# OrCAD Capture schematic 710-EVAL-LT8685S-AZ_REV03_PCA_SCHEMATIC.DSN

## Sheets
1 LT8685S: size Custom; note: 42V,QUAD GANGABLE,
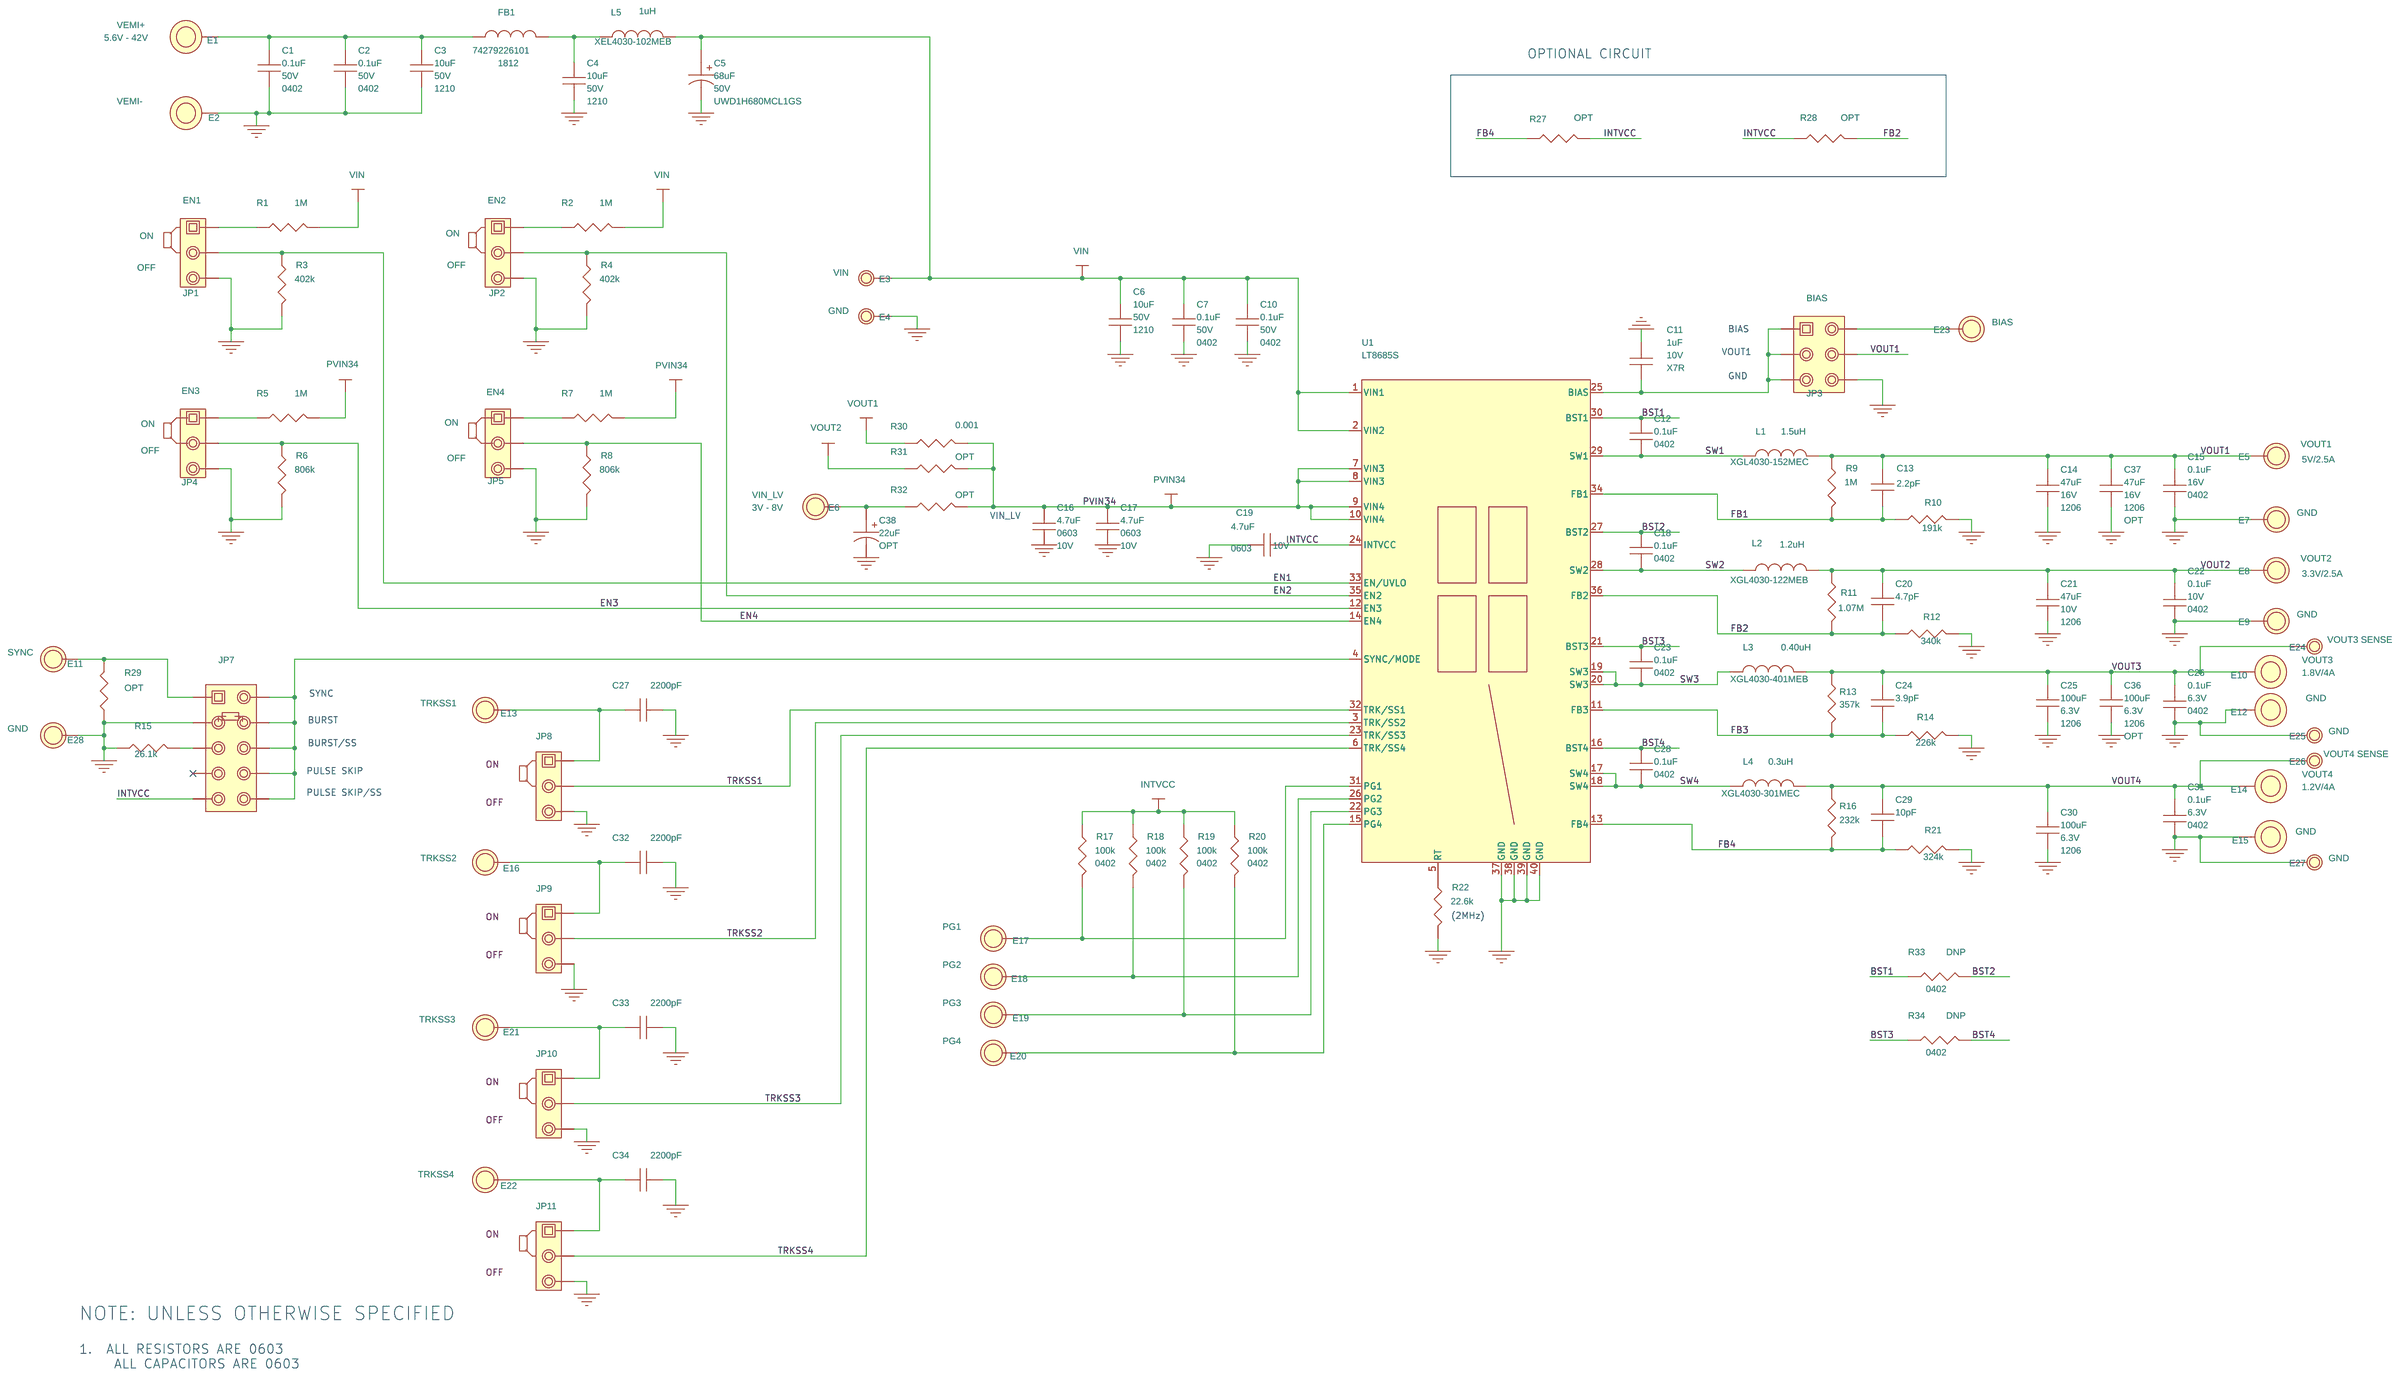
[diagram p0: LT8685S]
2 PAGE2
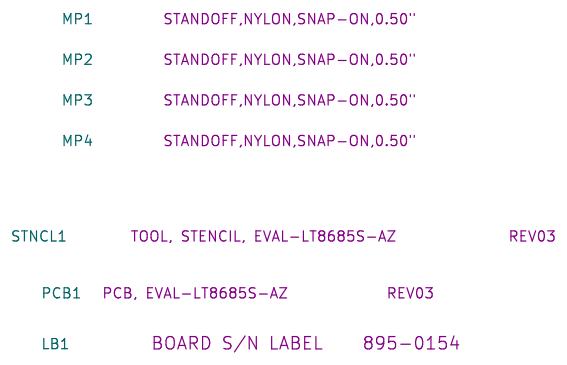
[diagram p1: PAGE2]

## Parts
sheet LT8685S
C1  0.1uF  [CC0402N]
C2  0.1uF  [CC0402N]
C3  10uF  [CC1210N]
C4  10uF  [CC1210N]
C5  68uF  [NICHICON_UWD_8x10]
C6  10uF  [CC1210N]
C7  0.1uF  [CC0402N]
C10  0.1uF  [CC0402N]
C11  1uF  [CC0603N]
C12  0.1uF  [CC0402N]
C13  2.2pF  [CC0603N]
C14  47uF  [CC1206N]
C15  0.1uF  [CC0402N]
C16  4.7uF  [CC0603N]
C17  4.7uF  [CC0603N]
C18  0.1uF  [CC0402N]
C19  4.7uF  [CC0603N]
C20  4.7pF  [CC0603N]
C21  47uF  [CC1206N]
C22  0.1uF  [CC0402N]
C23  0.1uF  [CC0402N]
C24  3.9pF  [CC0603N]
C25  100uF  [CC1206N]
C26  0.1uF  [CC0402N]
C27  2200pF  [CC0603N]
C28  0.1uF  [CC0402N]
C29  10pF  [CC0603N]
C30  100uF  [CC1206N]
C31  0.1uF  [CC0402N]
C32  2200pF  [CC0603N]
C33  2200pF  [CC0603N]
C34  2200pF  [CC0603N]
C36  100uF  [CC1206N]
C37  47uF  [CC1206N]
C38  22uF  [SUNCON_CE-BSS_6.3X5.4]
E1  BANANA JACK  [KEY-575-4]
E2  BANANA JACK  [KEY-575-4]
E3  TEST POINT  [MILLMAX2308]
E4  TEST POINT  [MILLMAX2308]
E5  TEST POINT  [MILLMAX2501]
E6  TEST POINT  [MILLMAX2501]
E7  TEST POINT  [MILLMAX2501]
E8  TEST POINT  [MILLMAX2501]
E9  TEST POINT  [MILLMAX2501]
E10  BANANA JACK  [KEY-575-4]
E11  TEST POINT  [MILLMAX2501]
E12  BANANA JACK  [KEY-575-4]
E13  TEST POINT  [MILLMAX2501]
E14  BANANA JACK  [KEY-575-4]
E15  BANANA JACK  [KEY-575-4]
E16  TEST POINT  [MILLMAX2501]
E17  TEST POINT  [MILLMAX2501]
E18  TEST POINT  [MILLMAX2501]
E19  TEST POINT  [MILLMAX2501]
E20  TEST POINT  [MILLMAX2501]
E21  TEST POINT  [MILLMAX2501]
E22  TEST POINT  [MILLMAX2501]
E23  TEST POINT  [MILLMAX2501]
E24  TEST POINT  [MILLMAX2308]
E25  TEST POINT  [MILLMAX2308]
E26  TEST POINT  [MILLMAX2308]
E27  TEST POINT  [MILLMAX2308]
E28  TEST POINT  [MILLMAX2501]
FB1  100 OHMS@100MHz  [WURTH-1812]
JP1  HDR  [HD1X3-079]
JP2  HDR  [HD1X3-079]
JP3  HDR  [HD2X3-079]
JP4  HDR  [HD1X3-079]
JP5  HDR  [HD1X3-079]
JP7  HDR  [HD2X5-079]
JP8  HDR  [HD1X3-079]
JP9  HDR  [HD1X3-079]
JP10  HDR  [HD1X3-079]
JP11  HDR  [HD1X3-079]
L1  1.5uH  [COILCRAFT-XGL4030]
L2  1.2uH  [COILCRAFT-XGL4030]
L3  0.40uH  [COILCRAFT-XGL4030]
L4  0.3uH  [COILCRAFT-XGL4030]
L5  1uH  [COILCRAFT-XEL4030]
R1  1M  [CR0603N]
R2  1M  [CR0603N]
R3  402k  [CR0603N]
R4  402k  [CR0603N]
R5  1M  [CR0603N]
R6  806k  [CR0603N]
R7  1M  [CR0603N]
R8  806k  [CR0603N]
R9  1M  [CR0603N]
R10  191k  [CR0603N]
R11  1.07M  [CR0603N]
R12  340k  [CR0603N]
R13  357k  [CR0603N]
R14  226k  [CR0603N]
R15  26.1k  [CR0603N]
R16  232k  [CR0603N]
R17  100k  [CR0402N]
R18  100k  [CR0402N]
R19  100k  [CR0402N]
R20  100k  [CR0402N]
R21  324k  [CR0603N]
R22  22.6k  [CR0603N]
R27  OPT  [CR0603N]
R28  OPT  [CR0603N]
R29  OPT  [CR0603N]
R30  0.001  [SUSUMU-KRL2012]
R31  0.001  [SUSUMU-KRL2012]
R32  0.001  [SUSUMU-KRL2012]
R33  OPT  [CR0402N]
R34  OPT  [CR0402N]
U1  LT8685S  [LTC-LQFN-36-7056]
XJP1  SHUNT
XJP2  SHUNT
XJP3  SHUNT
XJP4  SHUNT
XJP5  SHUNT
XJP7  SHUNT
XJP8  SHUNT
XJP9  SHUNT
XJP10  SHUNT
XJP11  SHUNT
sheet PAGE2
LB1  LABEL  [895-0154_REV01]
MP1  STANDOFF  [KEYSTONE_8829-8834]
MP2  STANDOFF  [KEYSTONE_8829-8834]
MP3  STANDOFF  [KEYSTONE_8829-8834]
MP4  STANDOFF  [KEYSTONE_8829-8834]
PCB1  PCB, EVAL-LT8685S-AZ
STNCL1  TOOL, STENCIL, EVAL-LT8685S-AZ

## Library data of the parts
C1 C2 C7 C10 = CAP: CAP.,0.1uF,X7R,50V,10%,0402; CLASS: DISCRETE; Dielectric Type: X7R; FPLIST: CC0402N,CC0402L,CC0402M; Inventory Qty: 321916; Manufacturer: AVX; Manufacturer PN: 04025C104KAT2A; PART_NUMBER: 150-3240; Package Size: 0402; Package Type: SMD; Rated Voltage: 50V; Tolerance: 10%
C3 C4 C6 = CAP: CAP.,10uF,X7R,50V,10%,1210,NO SUBS. ALLOWED; CLASS: DISCRETE; Dielectric Type: X7R; FPLIST: CC1210N,CC1210L,CC1210M; Inventory Qty: 191942; Manufacturer: MURATA; Manufacturer PN: GRM32ER71H106KA12L; PART_NUMBER: 150-3043; Package Size: 1210; Package Type: SMD; Rated Voltage: 50V; Tolerance: 10%
C5 = CAP_P_ALT: CAP.,68uF,ALUM ELECT.,50V,20%,SMD,8x10mm,AEC-Q200; CLASS: DISCRETE; Dielectric Type: ALUM ELECT.; Inventory Qty: 0; Manufacturer: Nichicon; Manufacturer PN: UWD1H680MCL1GS; PART_NUMBER: 150-1006; Package Size: SMD,8x10mm; Package Type: Surface Mount; Rated Voltage: 50V; Tolerance: 20%
C11 = CAP: CAP.,1uF,X7R,10V,10%,0603; CLASS: DISCRETE; Dielectric Type: X7R; FPLIST: CC0603N,CC0603L,CC0603M; Inventory Qty: 56548; Manufacturer: AVX; Manufacturer PN: 0603ZC105KAT2A; Material: X7R; PART_NUMBER: 150-3414; Package Size: 0603; Rated Voltage: 10V; Tolerance: 10%; Voltage Level: 10V
C12 C18 C23 C28 = CAP: CAP.,0.1uF,X7R,16V,10%,0402; CLASS: DISCRETE; Dielectric Type: X7R; FPLIST: CC0402N,CC0402L,CC0402M; Inventory Qty: 324549; Manufacturer: AVX; Manufacturer PN: 0402YC104KAT2A; PART_NUMBER: 150-2081; Package Size: 0402; Rated Voltage: 16V; Tolerance: 10%
C13 = CAP: CAP.,2.2pF,C0G/NP0,50V,+/-0.25pF,0603; CLASS: DISCRETE; Dielectric Type: C0G/NP0; FPLIST: CC0603N,CC0603L,CC0603M; Inventory Qty: 13646; Manufacturer: AVX; Manufacturer PN: 06035A2R2CAT2A; PART_NUMBER: 150-0030; Package Size: 0603; Rated Voltage: 50V; Tolerance: +/-0.25pF
C14 = CAP: CAP.,47uF,X5R,16V,20%,1206; CLASS: DISCRETE; Dielectric Type: X5R; FPLIST: CC1206N,CC1206L,CC1206M; Inventory Qty: 4594; Manufacturer: AVX; Manufacturer PN: 1206YD476MAT2A; Material: X7R; PART_NUMBER: 150-3243; Package Size: 1206; Package Type: SMD; Rated Voltage: 16V; Tolerance: 20%; Voltage Level: 16V
C15 = CAP: CAP.,0.1uF,X7R,16V,10%,0402; CLASS: DISCRETE; Dielectric Type: X7R; FPLIST: CC0402N,CC0402L,CC0402M; Inventory Qty: 324549; Manufacturer: AVX; Manufacturer PN: 0402YC104KAT2A; Material: X7R; PART_NUMBER: 150-2081; Package Size: 0402; Rated Voltage: 16V; Tolerance: 10%; Voltage Level: 16V
C16 C17 C19 = CAP: CAP.,4.7uF,X5R,10V,10%,0603; CLASS: DISCRETE; Dielectric Type: X5R; FPLIST: CC0603N,CC0603L,CC0603M; Inventory Qty: 20774; Manufacturer: AVX; Manufacturer PN: 0603ZD475KAT2A; Material: X7R; PART_NUMBER: 150-3050; Package Size: 0603; Rated Voltage: 10V; Tolerance: 10%; Voltage Level: 10V
C20 = CAP: CAP.,4.7pF,C0G/NP0,50V,+/-0.25pF,0603; CLASS: DISCRETE; Dielectric Type: C0G/NP0; FPLIST: CC0603N,CC0603L,CC0603M; Inventory Qty: 22709; Manufacturer: MURATA; Manufacturer PN: GRM1885C1H4R7CA01D; PART_NUMBER: 150-2223; Package Size: 0603; Rated Voltage: 50V; Tolerance: +/-0.25pF
C21 = CAP: CAP.,47uF,X5R,10V,10%,1206; CLASS: DISCRETE; Dielectric Type: X5R; FPLIST: CC1206N,CC1206L,CC1206M; Inventory Qty: 3750; Manufacturer: MURATA; Manufacturer PN: GRM31CR61A476KE15L; Material: X7R; PART_NUMBER: 150-3310; Package Size: 1206; Rated Voltage: 10V; Tolerance: 10%; Voltage Level: 10V
C22 = CAP: CAP.,0.1uF,X7R,10V,10%,0402; CLASS: DISCRETE; Dielectric Type: X7R; FPLIST: CC0402N,CC0402L,CC0402M; Inventory Qty: 92320; Manufacturer: MURATA; Manufacturer PN: GRM155R71A104KA01D; Material: X7R; PART_NUMBER: 150-0331; Package Size: 0402; Rated Voltage: 10V; Tolerance: 10%; Voltage Level: 10V
C24 = CAP: CAP.,3.9pF,C0G,50V,5%,0603; CLASS: DISCRETE; Dielectric Type: C0G; FPLIST: CC0603N,CC0603L,CC0603M; Inventory Qty: 202; Manufacturer: AVX; Manufacturer PN: 06035A3R9JAT2A; PART_NUMBER: 150-0276; Package Size: 0603; Rated Voltage: 50V; Tolerance: 5%
C25 C30 = CAP: CAP.,100uF,X5R,6.3V,10%,1206; CLASS: DISCRETE; Dielectric Type: X5R; FPLIST: CC1206N,CC1206L,CC1206M; Inventory Qty: 5866; Manufacturer: MURATA; Manufacturer PN: GRM31CR60J107KE39L; PART_NUMBER: 150-2327; Package Size: 1206; Rated Voltage: 6.3V; Tolerance: 10%
C26 C31 = CAP: CAP.,0.1uF,X5R,6.3V,20%,0402; CLASS: DISCRETE; Dielectric Type: X5R; FPLIST: CC0402N,CC0402L,CC0402M; Inventory Qty: 716; Manufacturer: AVX; Manufacturer PN: 04026D104MAT2A; Material: X7R; PART_NUMBER: 150-0498; Package Size: 0402; Rated Voltage: 6.3V; Tolerance: 20%; Voltage Level: 6.3V
C27 C32-C34 = CAP: CAP.,2200pF,X7R,25V,10%,0603; CLASS: DISCRETE; Dielectric Type: X7R; FPLIST: CC0603N,CC0603L,CC0603M; Inventory Qty: 24218; Manufacturer: AVX; Manufacturer PN: 06033C222KAT2A; PART_NUMBER: 150-2372; Package Size: 0603; Rated Voltage: 25V; Tolerance: 10%
C29 = CAP: CAP.,10pF,C0G,50V,5%,0603; CLASS: DISCRETE; Dielectric Type: C0G; FPLIST: CC0603N,CC0603L,CC0603M; Inventory Qty: 6220; Manufacturer: AVX; Manufacturer PN: 06035A100JAT2A; PART_NUMBER: 150-0023; Package Size: 0603; Rated Voltage: 50V; Tolerance: 5%
C36 = CAP: CAP.,100uF,X5R,6.3V,10%,1206; CLASS: DISCRETE; Dielectric Type: X5R; FPLIST: CC1206N,CC1206L,CC1206M; Inventory Qty: 5866; Manufacturer: MURATA; Manufacturer PN: GRM31CR60J107KE39L; PART_FIELD_01: OPT; PART_NUMBER: 150-2327; Package Size: 1206; Rated Voltage: 6.3V; Tolerance: 10%
C37 = CAP: CAP.,47uF,X5R,16V,20%,1206; CLASS: DISCRETE; Dielectric Type: X5R; FPLIST: CC1206N,CC1206L,CC1206M; Inventory Qty: 4594; Manufacturer: AVX; Manufacturer PN: 1206YD476MAT2A; Material: X7R; PART_FIELD_01: OPT; PART_NUMBER: 150-3243; Package Size: 1206; Package Type: SMD; Rated Voltage: 16V; Tolerance: 20%; Voltage Level: 16V
C38 = CAP_P_ALT: CAP.,22uF,ALUM ELECT,50V,20%,6.3x5.4mm,RADIAL,SMD,CE-BSS Series,AEC-Q200; 9th Part Field: OPT; CLASS: DISCRETE; Dielectric Type: ALUM ELECT; FPLIST: SUNCON_CE-BSS_6.3X5.4,SUNCON_CE-BSS_6-3X5-4; Inventory Qty: 290; Manufacturer: SUN ELECTRONIC INDUSTRIES CORP; Manufacturer PN: 50CE22BSS; PART_NUMBER: 150-3499; Package Size: 6.3x5.4mm,RADIAL,SMD; Rated Voltage: 50V; Tolerance: 20%
E1 = BANANA_KEYSTONE-575-4: CONN.,BANANA JACK,FEMALE,THT,NON-INSULATED,SWAGE,0.218"; CLASS: IO; Inventory Qty: 203061; Manufacturer: KEYSTONE; Manufacturer PN: 575-4; PART_FIELD_01: VEMI+; PART_FIELD_02: 5.6V - 42V; PART_NUMBER: 250-0428
E2 = BANANA_KEYSTONE-575-4: CONN.,BANANA JACK,FEMALE,THT,NON-INSULATED,SWAGE,0.218"; CLASS: IO; Inventory Qty: 203061; Manufacturer: KEYSTONE; Manufacturer PN: 575-4; PART_FIELD_01: VEMI-; PART_FIELD_02: 3V - 42V; PART_NUMBER: 250-0428
E3 = TEST_POINT_.156_MILL-MAX_2308_A: TEST POINT,TURRET,0.064" MTG. HOLE,PCB 0.062" THK; CLASS: IO; Inventory Qty: 1142083; Manufacturer: MILL-MAX; Manufacturer PN: 2308-2-00-80-00-00-07-0; PART_FIELD_1: VIN; PART_NUMBER: 260-0004
E4 E25 E27 = TEST_POINT_.156_MILL-MAX_2308_A: TEST POINT,TURRET,0.064" MTG. HOLE,PCB 0.062" THK; CLASS: IO; Inventory Qty: 1142083; Manufacturer: MILL-MAX; Manufacturer PN: 2308-2-00-80-00-00-07-0; PART_FIELD_1: GND; PART_NUMBER: 260-0004
E5 = TURRET_A: TEST POINT,TURRET,0.094" MTG. HOLE,PCB 0.062" THK; CLASS: IO; Inventory Qty: 823526; Manufacturer: MILL-MAX; Manufacturer PN: 2501-2-00-80-00-00-07-0; PART_FIELD_01: VOUT1; PART_FIELD_02: 5V/2.5A; PART_NUMBER: 260-0003
E6 = TURRET_A: TEST POINT,TURRET,0.094" MTG. HOLE,PCB 0.062" THK; CLASS: IO; Inventory Qty: 823526; Manufacturer: MILL-MAX; Manufacturer PN: 2501-2-00-80-00-00-07-0; PART_FIELD_01: VIN_LV; PART_FIELD_02: 3V - 8V; PART_NUMBER: 260-0003
E7 E9 E28 = TURRET_A: TEST POINT,TURRET,0.094" MTG. HOLE,PCB 0.062" THK; CLASS: IO; Inventory Qty: 823526; Manufacturer: MILL-MAX; Manufacturer PN: 2501-2-00-80-00-00-07-0; PART_FIELD_01: GND; PART_NUMBER: 260-0003
E8 = TURRET_A: TEST POINT,TURRET,0.094" MTG. HOLE,PCB 0.062" THK; CLASS: IO; Inventory Qty: 823526; Manufacturer: MILL-MAX; Manufacturer PN: 2501-2-00-80-00-00-07-0; PART_FIELD_01: VOUT2; PART_FIELD_02: 3.3V/2.5A; PART_NUMBER: 260-0003
E10 = BANANA_KEYSTONE-575-4: CONN.,BANANA JACK,FEMALE,THT,NON-INSULATED,SWAGE,0.218"; CLASS: IO; Inventory Qty: 203061; Manufacturer: KEYSTONE; Manufacturer PN: 575-4; PART_FIELD_01: VOUT3; PART_FIELD_02: 1.8V/4A; PART_NUMBER: 250-0428
E11 = TURRET_A: TEST POINT,TURRET,0.094" MTG. HOLE,PCB 0.062" THK; CLASS: IO; Inventory Qty: 823526; Manufacturer: MILL-MAX; Manufacturer PN: 2501-2-00-80-00-00-07-0; PART_FIELD_01: SYNC; PART_NUMBER: 260-0003
E12 E15 = BANANA_KEYSTONE-575-4: CONN.,BANANA JACK,FEMALE,THT,NON-INSULATED,SWAGE,0.218"; CLASS: IO; Inventory Qty: 203061; Manufacturer: KEYSTONE; Manufacturer PN: 575-4; PART_FIELD_01: GND; PART_FIELD_02: 5V/2A; PART_NUMBER: 250-0428
E13 = TURRET_A: TEST POINT,TURRET,0.094" MTG. HOLE,PCB 0.062" THK; CLASS: IO; Inventory Qty: 823526; Manufacturer: MILL-MAX; Manufacturer PN: 2501-2-00-80-00-00-07-0; PART_FIELD_01: TRKSS1; PART_NUMBER: 260-0003
E14 = BANANA_KEYSTONE-575-4: CONN.,BANANA JACK,FEMALE,THT,NON-INSULATED,SWAGE,0.218"; CLASS: IO; Inventory Qty: 203061; Manufacturer: KEYSTONE; Manufacturer PN: 575-4; PART_FIELD_01: VOUT4; PART_FIELD_02: 1.2V/4A; PART_NUMBER: 250-0428
E16 = TURRET_A: TEST POINT,TURRET,0.094" MTG. HOLE,PCB 0.062" THK; CLASS: IO; Inventory Qty: 823526; Manufacturer: MILL-MAX; Manufacturer PN: 2501-2-00-80-00-00-07-0; PART_FIELD_01: TRKSS2; PART_NUMBER: 260-0003
E17 = TURRET_A: TEST POINT,TURRET,0.094" MTG. HOLE,PCB 0.062" THK; CLASS: IO; Inventory Qty: 823526; Manufacturer: MILL-MAX; Manufacturer PN: 2501-2-00-80-00-00-07-0; PART_FIELD_01: PG1; PART_NUMBER: 260-0003
E18 = TURRET_A: TEST POINT,TURRET,0.094" MTG. HOLE,PCB 0.062" THK; CLASS: IO; Inventory Qty: 823526; Manufacturer: MILL-MAX; Manufacturer PN: 2501-2-00-80-00-00-07-0; PART_FIELD_01: PG2; PART_NUMBER: 260-0003
E19 = TURRET_A: TEST POINT,TURRET,0.094" MTG. HOLE,PCB 0.062" THK; CLASS: IO; Inventory Qty: 823526; Manufacturer: MILL-MAX; Manufacturer PN: 2501-2-00-80-00-00-07-0; PART_FIELD_01: PG3; PART_NUMBER: 260-0003
E20 = TURRET_A: TEST POINT,TURRET,0.094" MTG. HOLE,PCB 0.062" THK; CLASS: IO; Inventory Qty: 823526; Manufacturer: MILL-MAX; Manufacturer PN: 2501-2-00-80-00-00-07-0; PART_FIELD_01: PG4; PART_NUMBER: 260-0003
E21 = TURRET_A: TEST POINT,TURRET,0.094" MTG. HOLE,PCB 0.062" THK; CLASS: IO; Inventory Qty: 823526; Manufacturer: MILL-MAX; Manufacturer PN: 2501-2-00-80-00-00-07-0; PART_FIELD_01: TRKSS3; PART_NUMBER: 260-0003
E22 = TURRET_A: TEST POINT,TURRET,0.094" MTG. HOLE,PCB 0.062" THK; CLASS: IO; Inventory Qty: 823526; Manufacturer: MILL-MAX; Manufacturer PN: 2501-2-00-80-00-00-07-0; PART_FIELD_01: TRKSS4; PART_NUMBER: 260-0003
E23 = TURRET_A: TEST POINT,TURRET,0.094" MTG. HOLE,PCB 0.062" THK; CLASS: IO; Inventory Qty: 823526; Manufacturer: MILL-MAX; Manufacturer PN: 2501-2-00-80-00-00-07-0; PART_FIELD_01: BIAS; PART_NUMBER: 260-0003
E24 = TEST_POINT_.156_MILL-MAX_2308_A: TEST POINT,TURRET,0.064" MTG. HOLE,PCB 0.062" THK; CLASS: IO; Inventory Qty: 1142083; Manufacturer: MILL-MAX; Manufacturer PN: 2308-2-00-80-00-00-07-0; PART_FIELD_1: VOUT3 SENSE; PART_NUMBER: 260-0004
E26 = TEST_POINT_.156_MILL-MAX_2308_A: TEST POINT,TURRET,0.064" MTG. HOLE,PCB 0.062" THK; CLASS: IO; Inventory Qty: 1142083; Manufacturer: MILL-MAX; Manufacturer PN: 2308-2-00-80-00-00-07-0; PART_FIELD_1: VOUT4 SENSE; PART_NUMBER: 260-0004
FB1 = IND: IND.,100 OHMS@100MHz,FERRITE BEAD,25%,8A,6mOHMS,1812; CLASS: DISCRETE; FPLIST: WURTH-1812,WURTH-74279226101; Inventory Qty: 3043; Manufacturer: WURTH ELEKTRONIK; Manufacturer PN: 74279226101; PART_NUMBER: 200-0280; Package Size: 1812; Tolerance: 25%
JP1 = 1X3_A: CONN.,HDR,MALE,1x3,2mm,VERT,ST,THT,NO SUBS. ALLOWED; 10th Part Field: ON; 11th Part Field: OFF; 12th Part Field: 12th; 9th Part Field: EN1; CLASS: IO; Inventory Qty: 28997; Manufacturer: Wurth Elektronik; Manufacturer PN: 62000311121; PART_NUMBER: 250-0639
JP2 = 1X3_A: CONN.,HDR,MALE,1x3,2mm,VERT,ST,THT,NO SUBS. ALLOWED; 10th Part Field: ON; 11th Part Field: OFF; 12th Part Field: 12th; 9th Part Field: EN2; CLASS: IO; Inventory Qty: 28997; Manufacturer: Wurth Elektronik; Manufacturer PN: 62000311121; PART_NUMBER: 250-0639
JP3 = HDR2X3_ALT1: CONN.,HDR,MALE,2x3,2mm,VERT,ST,THT; 9th Part Field: BIAS; CLASS: IO; Inventory Qty: 17651; Manufacturer: WURTH ELEKTRONIK; Manufacturer PN: 62000621121; PART_NUMBER: 250-0483
JP4 = 1X3_A: CONN.,HDR,MALE,1x3,2mm,VERT,ST,THT,NO SUBS. ALLOWED; 10th Part Field: ON; 11th Part Field: OFF; 12th Part Field: 12th; 9th Part Field: EN3; CLASS: IO; Inventory Qty: 28997; Manufacturer: Wurth Elektronik; Manufacturer PN: 62000311121; PART_NUMBER: 250-0639
JP5 = 1X3_A: CONN.,HDR,MALE,1x3,2mm,VERT,ST,THT,NO SUBS. ALLOWED; 10th Part Field: ON; 11th Part Field: OFF; 12th Part Field: 12th; 9th Part Field: EN4; CLASS: IO; Inventory Qty: 28997; Manufacturer: Wurth Elektronik; Manufacturer PN: 62000311121; PART_NUMBER: 250-0639
JP7 = HDR2X5_ALT1: CONN.,HDR,MALE,2x5,2mm,VERT,ST,THT; CLASS: IO; Inventory Qty: 246; Manufacturer: WURTH ELEKTRONIK; Manufacturer PN: 62001021121; PART_NUMBER: 250-0679
JP8-JP11 = 1X3_A: CONN.,HDR,MALE,1x3,2mm,VERT,ST,THT,NO SUBS. ALLOWED; 10th Part Field: 10th; 11th Part Field: 11th; 12th Part Field: 12th; 9th Part Field: 9th; CLASS: IO; Inventory Qty: 28997; Manufacturer: Wurth Elektronik; Manufacturer PN: 62000311121; PART_NUMBER: 250-0639
L1 = IND: IND.,1.5uH,PWR,20%,10.2A,10.5mOHMS,SMD,AEC-Q200; CLASS: DISCRETE; Inventory Qty: 0; Manufacturer: COILCRAFT; Manufacturer PN: XGL4030-152MEC; PART_NUMBER: 200-0423; Package Size: SMD; Tolerance: 20%
L2 = IND: IND.,1.2uH,PWR,20%,12.2A,9.4mOHMS,SMD,AEC-Q200,SHIELDED; CLASS: DISCRETE; Inventory Qty: 0; Manufacturer: COILCRAFT; Manufacturer PN: XGL4030-122MEB; PART_NUMBER: 200-0407; Package Size: SMD; Tolerance: 20%
L3 = IND: IND.,0.40uH,PWR,20%,22.5A,32.8mOHMS,SMD,AEC-Q200; CLASS: DISCRETE; Inventory Qty: 0; Manufacturer: COILCRAFT; Manufacturer PN: XGL4030-401MEB; PART_NUMBER: 200-0422; Package Size: SMD; Tolerance: 20%
L4 = IND: IND.,0.3uH,PWR,20%,21.2A,3.4mOHMS,SMD,AEC-Q200,SHIELDED; CLASS: DISCRETE; Inventory Qty: 0; Manufacturer: COILCRAFT; Manufacturer PN: XGL4030-301MEC; PART_NUMBER: 200-0841; Package Size: SMD; Tolerance: 20%
L5 = IND: IND.,1uH,PWR,SHIELDED,20%,10.7A,9.78mOHMS,4.3x4.3mm,XEL4030,AEC-Q200; CLASS: DISCRETE; Inventory Qty: 0; Manufacturer: COILCRAFT; Manufacturer PN: XEL4030-102MEB; PART_NUMBER: 200-0762; Package Size: 4.3x4.3mm,XEL4030; Tolerance: 20%
R1 R2 R5 R7 R9 = RES: RES.,1M OHM,1%,1/10W,0603; CLASS: DISCRETE; FPLIST: CR0603N,CR0603L,CR0603M; Inventory Qty: 165718; Manufacturer: VISHAY; Manufacturer PN: CRCW06031M00FKEA; PART_NUMBER: 100-0335; Package Size: 0603; Rated Power: 1/10W; Temperature Coefficient: 100ppm; Tolerance: 1%
R3 R4 = RES: RES.,402k OHMS,1%,1/10W,0603,AEC-Q200; CLASS: DISCRETE; FPLIST: CR0603N,CR0603L,CR0603M; Inventory Qty: 13000; Manufacturer: NIC; Manufacturer PN: NRC06F4023TRF; PART_NUMBER: 100-2593; Package Size: 0603; Rated Power: 1/10W; Temperature Coefficient: 100ppm/C; Tolerance: 1%
R6 R8 = RES: RES.,806k OHMS,1%,1/10W,0603,AEC-Q200; CLASS: DISCRETE; FPLIST: CR0603N,CR0603L,CR0603M; Inventory Qty: 20000; Manufacturer: NIC; Manufacturer PN: NRC06F8063TRF; PART_NUMBER: 100-2599; Package Size: 0603; Rated Power: 1/10W; Temperature Coefficient: 100ppm/C; Tolerance: 1%
R10 = RES: RES.,191k OHMS,1%,1/10W,0603; CLASS: DISCRETE; FPLIST: CR0603N,CR0603L,CR0603M; Inventory Qty: 34532; Manufacturer: VISHAY; Manufacturer PN: CRCW0603191KFKEA; PART_NUMBER: 100-2371; Package Size: 0603; Rated Power: 1/10W; Temperature Coefficient: +/-100ppm; Tolerance: 1%
R11 = RES: RES.,1.07M OHMS,1%,1/10W,0603,AEC-Q200; CLASS: DISCRETE; FPLIST: CR0603N,CR0603L,CR0603M; Inventory Qty: 10000; Manufacturer: VISHAY; Manufacturer PN: CRCW06031M07FKEA; PART_NUMBER: 100-1786; Package Size: 0603; Rated Power: 1/10W; Temperature Coefficient: +/-100ppm; Tolerance: 1%
R12 = RES: RES.,340k OHMS,1%,1/10W,0603; CLASS: DISCRETE; FPLIST: CR0603N,CR0603L,CR0603M; Inventory Qty: 49500; Manufacturer: VISHAY; Manufacturer PN: CRCW0603340KFKEA; PART_NUMBER: 100-2674; Package Size: 0603; Rated Power: 1/10W; Temperature Coefficient: 100ppm/C; Tolerance: 1%
R13 = RES: RES.,357k OHMS,1%,1/10W,0603,AEC-Q200; CLASS: DISCRETE; FPLIST: CR0603N,CR0603L,CR0603M; Inventory Qty: 34204; Manufacturer: PANASONIC; Manufacturer PN: ERJ3EKF3573V; PART_NUMBER: 100-0089; Package Size: 0603; Rated Power: 1/10W; Temperature Coefficient: 100ppm/C; Tolerance: 1%
R14 = RES: RES.,226k OHMS,1%,1/10W,0603; CLASS: DISCRETE; FPLIST: CR0603N,CR0603L,CR0603M; Inventory Qty: 26500; Manufacturer: NIC; Manufacturer PN: NRC06F2263TRF; PART_NUMBER: 100-2671; Package Size: 0603; Rated Power: 1/10W; Temperature Coefficient: 100ppm/C; Tolerance: 1%
R15 = RES: RES.,26.1k OHMS,1%,1/10W,0603,AEC-Q200; CLASS: DISCRETE; FPLIST: CR0603N,CR0603L,CR0603M; Inventory Qty: 34752; Manufacturer: NIC; Manufacturer PN: NRC06F2612TRF; PART_NUMBER: 100-0855; Package Size: 0603; Rated Power: 1/10W; Temperature Coefficient: 100ppm; Tolerance: 1%
R16 = RES: RES.,232k OHMS,1%,1/10W,0603,AEC-Q200; CLASS: DISCRETE; FPLIST: CR0603N,CR0603L,CR0603M; Inventory Qty: 48508; Manufacturer: PANASONIC; Manufacturer PN: ERJ3EKF2323V; PART_NUMBER: 100-2654; Package Size: 0603; Rated Power: 1/10W; Temperature Coefficient: 100ppm/C; Tolerance: 1%
R17-R20 = RES: RES.,100k OHMS,1%,1/16W,0402,AEC-Q200; CLASS: DISCRETE; FPLIST: CR0402N,CR0402L,CR0402M; Inventory Qty: 150967; Manufacturer: VISHAY; Manufacturer PN: CRCW0402100KFKED; PART_NUMBER: 100-2396; Package Size: 0402; Rated Power: 1/16W; Temperature Coefficient: 100ppm; Tolerance: 1%
R21 = RES: RES.,324k OHMS,1%,1/10W,0603,AEC-Q200; CLASS: DISCRETE; FPLIST: CR0603N,CR0603L,CR0603M; Inventory Qty: 10000; Manufacturer: VISHAY; Manufacturer PN: CRCW0603324KFKEA; PART_NUMBER: 100-0594; Package Size: 0603; Rated Power: 1/10W; Temperature Coefficient: 100ppm; Tolerance: 1%
R22 = RES: RES.,22.6k OHMS,1%,1/10W,0603; CLASS: DISCRETE; FPLIST: CR0603N,CR0603L,CR0603M; Inventory Qty: 5000; Manufacturer: NIC; Manufacturer PN: NRC06F2262TRF; PART_NUMBER: 100-2365; Package Size: 0603; Rated Power: 1/10W; Temperature Coefficient: 100ppm/C; Tolerance: 1%
R27-R29 = RES: RES., OPTION, 0603; CLASS: DISCRETE; FPLIST: CR0603N,CR0603L,CR0603M; PART_NUMBER: 100-2374; Package Size: 0603
R30 = RES: RES.,0.001 OHM,5%,1W,0805,LONG SIDE TERM,METAL,SENSE,AEC-Q200; CLASS: DISCRETE; Inventory Qty: 0; Manufacturer: SUSUMU; Manufacturer PN: KRL2012E-C-R001-J-T5; PART_NUMBER: 100-1874; Package Size: 0805,LONG SIDE TERM; Rated Power: 1W; Temperature Coefficient: +/-150ppm; Tolerance: 5%
R31 R32 = RES: RES.,0.001 OHM,5%,1W,0805,LONG SIDE TERM,METAL,SENSE,AEC-Q200; CLASS: DISCRETE; Inventory Qty: 0; Manufacturer: SUSUMU; Manufacturer PN: KRL2012E-C-R001-J-T5; PART_FIELD_01: OPT; PART_NUMBER: 100-1874; Package Size: 0805,LONG SIDE TERM; Rated Power: 1W; Temperature Coefficient: +/-150ppm; Tolerance: 5%
R33 R34 = RES: RES., OPTION, 0402; CLASS: DISCRETE; FPLIST: CR0402N,CR0402L,CR0402M; PART_FIELD_01: DNP; PART_NUMBER: 100-0357; Package Size: 0402
U1 = LT8685S-LQFN: IC,Monolithic Step-Down Regulator,LQFN-36,5x6mm; CLASS: IC; Inventory Qty: 0; Manufacturer: ANALOG DEVICES; Manufacturer PN: LT8685SJV#TRPBF; PART_NUMBER: LT8685SJV#TRPBF; Package Type: LQFN-36,5x6mm
XJP1 XJP2 XJP4 XJP5 XJP8-XJP11 = SHUNT_2MM: CONN.,SHUNT,FEMALE,2-POS,2mm; CLASS: IO; Comment1: ON; Comment2: OFF; Inventory Qty: 64675; Manufacturer: Wurth Elektronik; Manufacturer PN: 60800213421; PART_NUMBER: 250-0485
XJP3 XJP7 = SHUNT_2MM_C: CONN.,SHUNT,FEMALE,2-POS,2mm; CLASS: IO; Inventory Qty: 64675; Manufacturer: Wurth Elektronik; Manufacturer PN: 60800213421; PART_NUMBER: 250-0485
LB1 = BLANK_LABEL: LABEL SPEC, DEMO BOARD SERIAL NUMBER; Inventory Qty: 0; Manufacturer: BRADY; Manufacturer PN: THT-96-717-10; PART_FIELD_01: BOARD S/N LABEL; PART_NUMBER: 895-0154
MP1-MP4 = BLANK_MECHANICAL_PART: STANDOFF,NYLON,SNAP-ON,0.50"; CLASS: DISCRETE; FPLIST: KEYSTONE_8829-8834,KEYSTONE_8833,MTG-8831; Inventory Qty: 214842; Manufacturer: KEYSTONE; Manufacturer PN: 8833; PART_NUMBER: 763-0007
PCB1 = BLANK_PCB_PART: BOM Notes: REV03; CLASS: DISCRETE; Inventory Qty: 0; Manufacturer: ADI APPROVED SUPPLIER; Manufacturer PN: 600-EVAL-LT8685S-AZ; PART_NUMBER: 600-EVAL-LT8685S-AZ
STNCL1 = BLANK_STENCIL_PART: BOM Notes: REV03; CLASS: DISCRETE; Inventory Qty: 0; Manufacturer: ADI APPROVED SUPPLIER; Manufacturer PN: 830-EVAL-LT8685S-AZ; PART_NUMBER: 830-EVAL-LT8685S-AZ

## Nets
GND: C1.2 C2.2 C3.2 C4.2 C5.2 C6.2 C7.2 C10.2 C11.2 C14.1 C15.1 C16.1 C17.1 C19.2 C21.1 C22.1 C25.2 C26.1 C27.2 C30.2 C31.1 C32.2 C33.2 C34.2 C36.2 C37.1 C38.2 E2.1 E4.1 E7.1 E9.1 E12.1 E15.1 E25.1 E27.1 E28.1 JP1.3 JP2.3 JP3.6 JP4.3 JP5.3 JP7.3 JP8.3 JP9.3 JP10.3 JP11.3 R3.2 R4.2 R6.2 R8.2 R10.2 R12.2 R14.2 R15.1 R21.2 R22.2 R29.1 U1.37(GND) U1.38(GND) U1.39(GND) U1.40(GND)
PVIN34: C16.2 C17.2 R5.2 R7.2 R30.2 R31.2 R32.2 U1.7(VIN3) U1.8(VIN3) U1.9(VIN4) U1.10(VIN4)
VIN: C5.1 C6.1 C7.1 C10.1 E3.1 L5.2 R1.2 R2.2 U1.1(VIN1) U1.2(VIN2)
BST1: C12.1 R33.1 U1.30(BST1)
BST2: C18.1 R33.2 U1.27(BST2)
BST3: C23.1 R34.1 U1.21(BST3)
BST4: C28.1 R34.2 U1.16(BST4)
EN1: JP1.2 R3.1 U1.33(EN/UVLO)
EN2: JP2.2 R4.1 U1.35(EN2)
EN3: JP4.2 R6.1 U1.12(EN3)
EN4: JP5.2 R8.1 U1.14(EN4)
FB1: C13.2 R9.2 R10.1 U1.34(FB1)
FB2: C20.2 R11.2 R12.1 R28.2 U1.36(FB2)
FB3: C24.2 R13.2 R14.1 U1.11(FB3)
FB4: C29.2 R16.2 R21.1 R27.1 U1.13(FB4)
INTVCC: C19.1 JP7.9 R17.1 R18.1 R19.1 R20.1 R27.2 R28.1 U1.24(INTVCC)
SW1: C12.2 L1.1 U1.29(SW1)
SW2: C18.2 L2.1 U1.28(SW2)
SW3: C23.2 L3.1 U1.19(SW3) U1.20(SW3)
SW4: C28.2 L4.1 U1.17(SW4) U1.18(SW4)
TRKSS1: JP8.2 U1.32(TRK/SS1)
TRKSS2: JP9.2 U1.3(TRK/SS2)
TRKSS3: JP10.2 U1.23(TRK/SS3)
TRKSS4: JP11.2 U1.6(TRK/SS4)
VOUT1: C13.1 C14.2 C15.2 C37.2 E5.1 JP3.4 L1.2 R9.1 R30.1
VOUT2: C20.1 C21.2 C22.2 E8.1 L2.2 R11.1 R31.1
VOUT3: C24.1 C25.1 C26.2 C36.1 E10.1 E24.1 L3.2 R13.1
VOUT4: C29.1 C30.1 C31.2 E14.1 E26.1 L4.2 R16.1
N03828: C11.1 JP3.1 JP3.3 JP3.5 U1.25(BIAS)
N14274: C27.1 E13.1 JP8.1
N15668: C32.1 E16.1 JP9.1
N15906: C33.1 E21.1 JP10.1
N16413: C34.1 E22.1 JP11.1
N19091: JP1.1 R1.1
N21270: E17.1 R17.2 U1.31(PG1)
N21288: E18.1 R18.2 U1.26(PG2)
N21315: E19.1 R19.2 U1.22(PG3)
N21342: E20.1 R20.2 U1.15(PG4)
N22681: JP2.1 R2.1
N22972: JP4.1 R5.1
N23272: JP5.1 R7.1
N16581618: E11.1 JP7.1 R29.2
N16592775: C1.1 C2.1 C3.1 E1.1 FB1.1
N16594761: C4.1 FB1.2 L5.1
N16608346: JP7.5 R15.2
N16608356: JP7.2 JP7.4 JP7.6 JP7.8 JP7.10 U1.4(SYNC/MODE)
N16684334: E23.1 JP3.2
N16718327: C38.1 E6.1 R32.1
N16763168: R22.1 U1.5(RT)

Not connected (* = marked no-connect by the designer): JP7 7*

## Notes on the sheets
sheet 1
- OPTIONAL CIRCUIT
- BIAS
- VOUT1
- GND
- VIN_LV
- SYNC
- BURST
- BURST/SS
- PULSE SKIP
- PULSE SKIP/SS
- (2MHz)
- NOTE: UNLESS OTHERWISE SPECIFIED
- 1.  ALL RESISTORS ARE 0603
       ALL CAPACITORS ARE 0603
